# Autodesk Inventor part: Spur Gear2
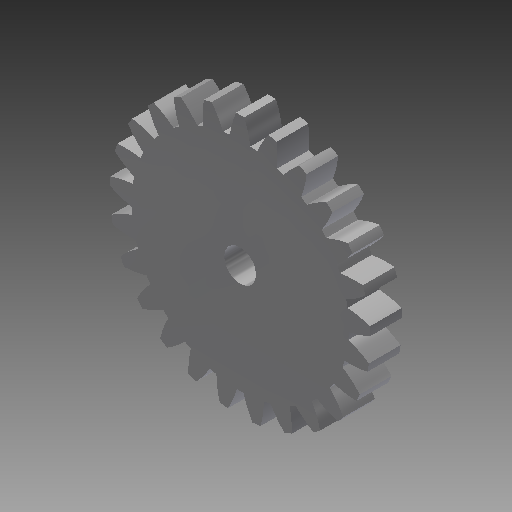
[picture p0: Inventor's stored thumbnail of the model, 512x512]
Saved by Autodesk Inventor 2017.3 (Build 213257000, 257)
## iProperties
Created: 2020-03
Part Number: Spur Gear2
Material: Steel
Document SubType Name: Modeling
Designer: Tim_G
Categories: <?xml version="1.0" encoding="UTF-16"?> <MemberInstance><Categories><FamilyTemplate><FamilyTemplateParameter ValueType="xs:double" Id="1" ObjectReferenceKey="da
Density: 1 g/cm^3
Appearance: Steel
CustomPartVersion: 1
Author: Tim_G
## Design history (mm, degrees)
sketch "Sketch1"
  geometry: C1 r 20.56 at (0, 0)
  constraints: 1 centre point
  dimensions: "d0" = 41.11927 diameter of C1 (= da_da)
extrude "Extrusion1" new body sketch "Sketch1" distance "d1" = 5 (= da_b); taper "d2" = 0 deg
workplane "Work Plane2"
sketch "Sketch2"
  geometry: C1 r 20.56 at (0, 0) reference; C2 r 19.037 at (0, 0)
  constraints: 1 centre point, 1 coincident
  dimensions: "d3" = 38.07339 diameter of C2 (= da_dw)
feature "Pitch Diameter" sketch "Sketch2" dims "d4" = 10, "d5" = 0
workplane "Work Plane8"
workplane "Work Plane9"
feature "Spur Gear" dims "da_b" = 5, "da_d" = 38.07339, "da_aw" = 28.17431, "da_da" = 41.11927, "da_df" = 34.26606, "da_dw" = 38.07339, angle "da_beta" = 0 deg, "da_lefttooth" = 0, "da_righttooth" = 0
sketch "Sketch3"
  geometry: C1 r 2.5 at (0, 0); 1 further point
  constraints: 1 centre point, 1 coincident
  dimensions: "d49" = 5 diameter of C1
extrude "Extrusion2" cut sketch "Sketch3" distance "d50" = 5; taper "d51" = 0 deg
body "Solid1"
body "Srf1"
other parameters: "d16" = 28.17431 (= da_aw), "d17" = 0, "d34" = 1.25664 (computed from da_z), "d39" = 0, "d41" = 0, "d43" = 28.17431 (= da_aw), "d46" = 28.17431 (= da_aw), "d47" = 0, "d48" = 0
